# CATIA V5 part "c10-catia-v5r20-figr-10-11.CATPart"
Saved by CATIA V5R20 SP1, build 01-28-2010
Part number: Part1
Bounding box of the stored display mesh (mm): x -100 to 0, y -100 to 90, z 0 to 33.63
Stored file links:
  D:\v5_r20\psrt_files_downloaded\c10\c10-catia-v5r20-figr-10-11.CATPart
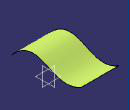
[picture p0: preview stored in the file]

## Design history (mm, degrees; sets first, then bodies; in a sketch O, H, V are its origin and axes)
Set1
  Sketch1 on face of yz-plane, origin (0, 0, 0), H (0, 0, -1), V (0, 1, 0)
    spline S1 through (0, -100) (-30, -20) (-10, 30) (-20, 90)
  Extrude1: Element1 Sketch1, Lim1 0, Lim2 100, Direction face of yz-plane
Body1 (main body)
